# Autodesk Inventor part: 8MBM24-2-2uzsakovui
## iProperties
Created: 2009-10
Part Number: 8MBM24-2-2uzsakovui
Document SubType Name: Modeling
Designer: Darius
Author: Darius
Translation Standard: STEP AP203
File Name: 8MBM24-2-2.STEP
Preprocessor: SolidWorks 2003240
Postprocessor: Build: 272, Release: 10 SP3a - Date: Thu 12/15/2005
Sent Units: MILLIMETERS
Uncertainty: 1e-05
